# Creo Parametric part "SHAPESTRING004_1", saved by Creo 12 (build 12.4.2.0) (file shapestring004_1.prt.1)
Units: Custom; MM, KILOGRAM, SECS

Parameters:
  PTC_WM_ITERATION = "0"
  PTC_WM_VERSION = "-.0"
  PTC_WM_LIFECYCLE_STATE = "In Work"
  PTC_WM_LIFECYCLE = "MO_CADDocument"
  PTC_WM_CREATED_BY = "Maximilian Roepper (Z0017RMS: MO)"
  PTC_WM_CREATED_ON = "18-Sep-26 11:36:42 AM"
  PTC_WM_MODIFIED_BY = "Maximilian Roepper (Z0017RMS: MO)"
  PTC_WM_MODIFIED_ON = "18-Sep-26 11:36:46 AM"
  PDMLINKNUMBER = "PDM000071455303"
  PTC_WM_NAME = "shapestring004_1.prt"
  PTC_WM_NUMBER = "PDM000071455303"

Other parameters: WEIGHT, WEIGHT_FACTOR, WEIGHT_ADD, _MASS_TEMP, _DIFF_TEMP, MC_ERRORS, SUPPLIER

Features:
  1. coordinate system
  2. datum plane "PRT_YZ"
  3. datum plane "PRT_XY"
  4. datum plane "PRT_XZ"
  5. coordinate system
  6. datum axis
  7. datum axis
  8. datum axis
  9. coordinate system
  10. imported feature
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
Other named items: PRT, SIEMENS_MO, DRW_VIEW_ORG, PRT_X, PRT_Y, PRT_Z, CS0, ROUGH_GROB

Layers: 00_STD_CSYS-KSYS, 01_STD_PLANES-EBENEN, 02_STD_AXES-ACHSEN, 03_STD_CSYS-KSYS, 24_IMPORT_FEAT-IMPORT_KE, WHITE

Surfaces: 1 plane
